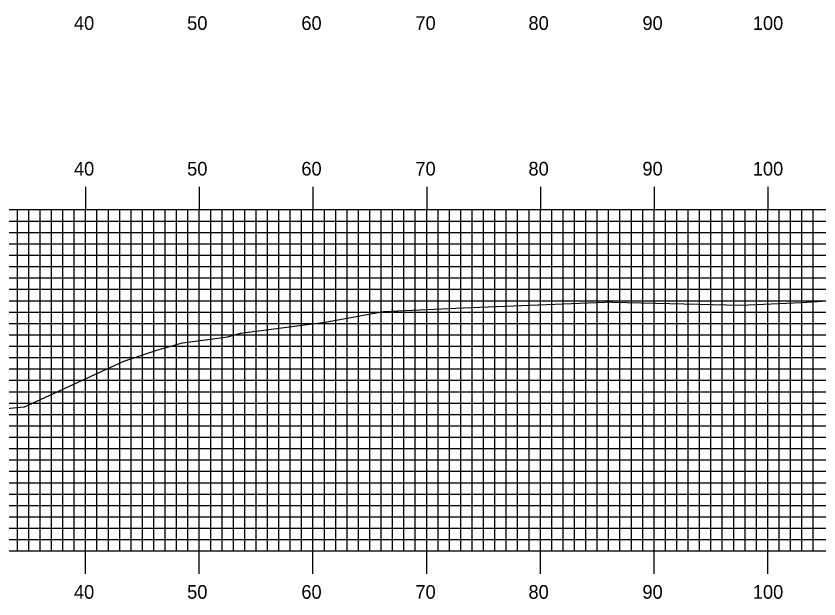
# Model space of a CAD drawing. Extents: x 850955 to 851298, y 364785 to 365005.
# Drawn here: x 851154.6 to 851225.2, y 364899 to 364950.3 of the extents above; entities that cross this region are included whole.
import ezdxf

# ---------------------------------------------------------------- set-up
doc = ezdxf.new("R2010")
doc.units = 0
for name, color, linetype in [('H_V ANNOTATION', 7, 'Continuous'), ('MAJOR', 7, 'Continuous'), ('MINOR', 7, 'Continuous'), ('S_Roadway_Centerline', 7, 'Continuous')]:
    doc.layers.add(name, color=color, linetype=linetype)

msp = doc.modelspace()

# ---------------------------------------------------------------- linework, layer by layer
at = {"layer": 'MAJOR'}
for p, q in [((851160.678, 364935.237), (851160.678, 364933.233)), ((851170.678, 364935.237), (851170.678, 364933.233)), ((851180.678, 364935.237), (851180.678, 364933.233)), ((851190.678, 364935.237), (851190.678, 364933.233)), ((851200.678, 364935.237), (851200.678, 364933.233)), ((851210.678, 364935.237), (851210.678, 364933.233)), ((851220.678, 364935.237), (851220.678, 364933.233)), ((850980.678, 364933.233), (851260.678, 364933.233)), ((850980.678, 364933.233), (851260.678, 364933.233)), ((851160.678, 364903.233), (851160.678, 364933.233)), ((851170.678, 364903.233), (851170.678, 364933.233)), ((851180.678, 364903.233), (851180.678, 364933.233)), ((851190.678, 364903.233), (851190.678, 364933.233)), ((851200.678, 364903.233), (851200.678, 364933.233)), ((851210.678, 364903.233), (851210.678, 364933.233)), ((851220.678, 364903.233), (851220.678, 364933.233)), ((850980.678, 364928.233), (851260.678, 364928.233)), ((850980.678, 364923.233), (851260.678, 364923.233)), ((850980.678, 364918.233), (851260.678, 364918.233)), ((850980.678, 364913.233), (851260.678, 364913.233)), ((850980.678, 364908.233), (851260.678, 364908.233)), ((850980.678, 364903.233), (851260.678, 364903.233)), ((850980.678, 364903.233), (851260.678, 364903.233)), ((851160.678, 364901.229), (851160.678, 364903.233)), ((851170.678, 364901.229), (851170.678, 364903.233)), ((851180.678, 364901.229), (851180.678, 364903.233)), ((851190.678, 364901.229), (851190.678, 364903.233)), ((851200.678, 364901.229), (851200.678, 364903.233)), ((851210.678, 364901.229), (851210.678, 364903.233)), ((851220.678, 364901.229), (851220.678, 364903.233))]:
    msp.add_line(p, q, dxfattribs=at)
at = {"layer": 'MINOR'}
for p, q in [((851154.678, 364903.233), (851154.678, 364933.233)), ((851155.678, 364903.233), (851155.678, 364933.233)), ((851156.678, 364903.233), (851156.678, 364933.233)), ((851157.678, 364903.233), (851157.678, 364933.233)), ((851158.678, 364903.233), (851158.678, 364933.233)), ((851159.678, 364903.233), (851159.678, 364933.233)), ((851161.678, 364903.233), (851161.678, 364933.233)), ((851162.678, 364903.233), (851162.678, 364933.233)), ((851163.678, 364903.233), (851163.678, 364933.233)), ((851164.678, 364903.233), (851164.678, 364933.233)), ((851165.678, 364903.233), (851165.678, 364933.233)), ((851166.678, 364903.233), (851166.678, 364933.233)), ((851167.678, 364903.233), (851167.678, 364933.233)), ((851168.678, 364903.233), (851168.678, 364933.233)), ((851169.678, 364903.233), (851169.678, 364933.233)), ((851171.678, 364903.233), (851171.678, 364933.233)), ((851172.678, 364903.233), (851172.678, 364933.233)), ((851173.678, 364903.233), (851173.678, 364933.233)), ((851174.678, 364903.233), (851174.678, 364933.233)), ((851175.678, 364903.233), (851175.678, 364933.233)), ((851176.678, 364903.233), (851176.678, 364933.233)), ((851177.678, 364903.233), (851177.678, 364933.233)), ((851178.678, 364903.233), (851178.678, 364933.233)), ((851179.678, 364903.233), (851179.678, 364933.233)), ((851181.678, 364903.233), (851181.678, 364933.233)), ((851182.678, 364903.233), (851182.678, 364933.233)), ((851183.678, 364903.233), (851183.678, 364933.233)), ((851184.678, 364903.233), (851184.678, 364933.233)), ((851185.678, 364903.233), (851185.678, 364933.233)), ((851186.678, 364903.233), (851186.678, 364933.233)), ((851187.678, 364903.233), (851187.678, 364933.233)), ((851188.678, 364903.233), (851188.678, 364933.233)), ((851189.678, 364903.233), (851189.678, 364933.233)), ((851191.678, 364903.233), (851191.678, 364933.233)), ((851192.678, 364903.233), (851192.678, 364933.233)), ((851193.678, 364903.233), (851193.678, 364933.233)), ((851194.678, 364903.233), (851194.678, 364933.233)), ((851195.678, 364903.233), (851195.678, 364933.233)), ((851196.678, 364903.233), (851196.678, 364933.233)), ((851197.678, 364903.233), (851197.678, 364933.233)), ((851198.678, 364903.233), (851198.678, 364933.233)), ((851199.678, 364903.233), (851199.678, 364933.233)), ((851201.678, 364903.233), (851201.678, 364933.233)), ((851202.678, 364903.233), (851202.678, 364933.233)), ((851203.678, 364903.233), (851203.678, 364933.233)), ((851204.678, 364903.233), (851204.678, 364933.233)), ((851205.678, 364903.233), (851205.678, 364933.233)), ((851206.678, 364903.233), (851206.678, 364933.233)), ((851207.678, 364903.233), (851207.678, 364933.233)), ((851208.678, 364903.233), (851208.678, 364933.233)), ((851209.678, 364903.233), (851209.678, 364933.233)), ((851211.678, 364903.233), (851211.678, 364933.233)), ((851212.678, 364903.233), (851212.678, 364933.233)), ((851213.678, 364903.233), (851213.678, 364933.233)), ((851214.678, 364903.233), (851214.678, 364933.233)), ((851215.678, 364903.233), (851215.678, 364933.233)), ((851216.678, 364903.233), (851216.678, 364933.233)), ((851217.678, 364903.233), (851217.678, 364933.233)), ((851218.678, 364903.233), (851218.678, 364933.233)), ((851219.678, 364903.233), (851219.678, 364933.233)), ((851221.678, 364903.233), (851221.678, 364933.233)), ((851222.678, 364903.233), (851222.678, 364933.233)), ((851223.678, 364903.233), (851223.678, 364933.233)), ((851224.678, 364903.233), (851224.678, 364933.233)), ((850980.678, 364932.233), (851260.678, 364932.233)), ((850980.678, 364931.233), (851260.678, 364931.233)), ((850980.678, 364930.233), (851260.678, 364930.233)), ((850980.678, 364929.233), (851260.678, 364929.233)), ((850980.678, 364927.233), (851260.678, 364927.233)), ((850980.678, 364926.233), (851260.678, 364926.233)), ((850980.678, 364925.233), (851260.678, 364925.233)), ((850980.678, 364924.233), (851260.678, 364924.233)), ((850980.678, 364922.233), (851260.678, 364922.233)), ((850980.678, 364921.233), (851260.678, 364921.233)), ((850980.678, 364920.233), (851260.678, 364920.233)), ((850980.678, 364919.233), (851260.678, 364919.233)), ((850980.678, 364917.233), (851260.678, 364917.233)), ((850980.678, 364916.233), (851260.678, 364916.233)), ((850980.678, 364915.233), (851260.678, 364915.233)), ((850980.678, 364914.233), (851260.678, 364914.233)), ((850980.678, 364912.233), (851260.678, 364912.233)), ((850980.678, 364911.233), (851260.678, 364911.233)), ((850980.678, 364910.233), (851260.678, 364910.233)), ((850980.678, 364909.233), (851260.678, 364909.233)), ((850980.678, 364907.233), (851260.678, 364907.233)), ((850980.678, 364906.233), (851260.678, 364906.233)), ((850980.678, 364905.233), (851260.678, 364905.233)), ((850980.678, 364904.233), (851260.678, 364904.233))]:
    msp.add_line(p, q, dxfattribs=at)
at = {"layer": 'S_Roadway_Centerline'}
msp.add_lwpolyline([(851152.465, 364915.629), (851155.288, 364915.899), (851155.289, 364915.899), (851155.308, 364915.907), (851164.026, 364919.929), (851166.943, 364920.868), (851169.214, 364921.525), (851173.19, 364922.063), (851174.304, 364922.372), (851181.742, 364923.355), (851186.882, 364924.288), (851193.889, 364924.616), (851206.341, 364925.095), (851206.581, 364925.121), (851207.052, 364925.116), (851218.298, 364924.831), (851223.639, 364925.06), (851230.51, 364925.502), (851242.469, 364926.237), (851242.601, 364926.243), (851242.852, 364926.252), (851260.678, 364927.039)], dxfattribs=at)

# ---------------------------------------------------------------- texts
at = {"layer": 'H_V ANNOTATION'}
for s, p in [('40', (851159.651, 364949.033)), ('50', (851169.608, 364949.033)), ('60', (851179.651, 364949.033)), ('70', (851189.683, 364949.033)), ('80', (851199.629, 364949.033)), ('90', (851209.651, 364949.033)), ('100', (851219.362, 364949.033)), ('40', (851159.651, 364936.233)), ('50', (851169.608, 364936.233)), ('60', (851179.651, 364936.233)), ('70', (851189.683, 364936.233)), ('80', (851199.629, 364936.233)), ('90', (851209.651, 364936.233)), ('100', (851219.362, 364936.233)), ('40', (851159.651, 364899.033)), ('50', (851169.608, 364899.033)), ('60', (851179.651, 364899.033)), ('70', (851189.683, 364899.033)), ('80', (851199.629, 364899.033)), ('90', (851209.651, 364899.033)), ('100', (851219.362, 364899.033))]:
    msp.add_text(s, height=1.2, dxfattribs=at).set_placement(p)

doc.saveas('drawing.dxf')
